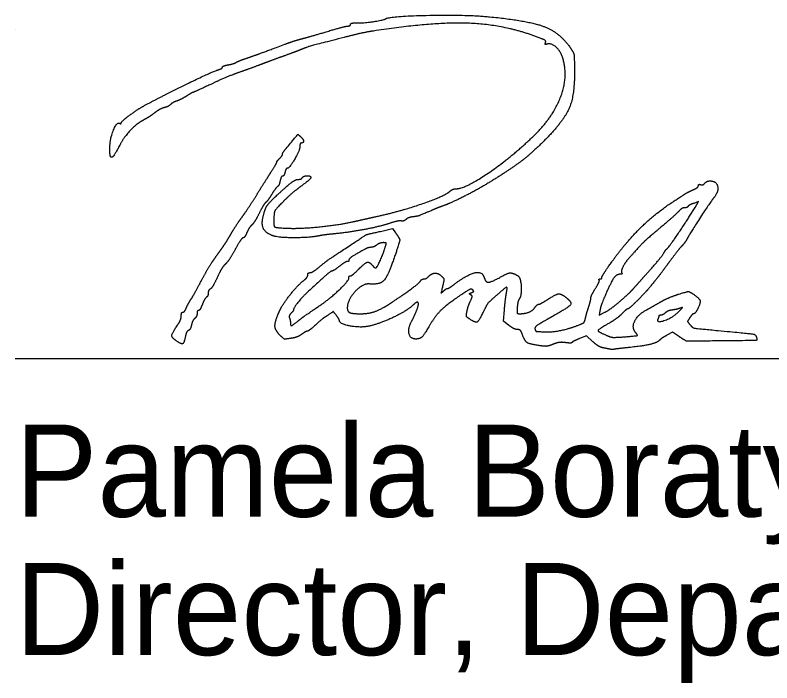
# Model space of a CAD drawing. Extents: x 0 to 48.6, y 0 to 22.
# Drawn here: x 24.528 to 25.676, y 7.305 to 8.318 of the extents above; entities that cross this region are included whole.
import ezdxf

# ---------------------------------------------------------------- set-up
doc = ezdxf.new("R2010")
doc.units = 0
for name, color, linetype in [('Default', 7, 'Continuous'), ('SH_Data', 7, 'Continuous'), ('SH_Text', 7, 'Continuous')]:
    doc.layers.add(name, color=color, linetype=linetype)

msp = doc.modelspace()

# ---------------------------------------------------------------- linework, layer by layer
at = {"layer": 'Default'}
for points in [[(25.5597, 8.0263), (25.5651, 8.0352), (25.5577, 8.0326)], [(25.0824, 7.9901), (25.1004, 7.9942), (25.1051, 7.988)], [(25.2773, 7.8473), (25.269, 7.8536), (25.2704, 7.8707)], [(25.4153, 7.8693), (25.4143, 7.8628), (25.4229, 7.8673)], [(25.5361, 7.83), (25.5255, 7.8368), (25.5171, 7.8323)], [(25.4043, 7.823), (25.3951, 7.8313), (25.3845, 7.8272)]]:
    msp.add_lwpolyline(points, dxfattribs=at)
for points in [[(25.0898, 8.3127), (25.0966, 8.3169), (25.2136, 8.3192), (25.248, 8.3158)], [(25.248, 8.3158), (25.3072, 8.31), (25.3548, 8.2917), (25.3706, 8.2686)], [(25.033, 8.3018), (25.0351, 8.3018), (25.0368, 8.3029), (25.0368, 8.3043)], [(25.0368, 8.3043), (25.0368, 8.3056), (25.0408, 8.3066), (25.0458, 8.3065)], [(25.0458, 8.3065), (25.0554, 8.3062), (25.0864, 8.3106), (25.0898, 8.3127)], [(25.3205, 8.285), (25.2699, 8.304), (25.1619, 8.308), (25.0716, 8.2942)], [(24.9612, 8.282), (24.9665, 8.2833), (24.9839, 8.2883), (25, 8.2931)], [(25, 8.2931), (25.0161, 8.2979), (25.031, 8.3018), (25.033, 8.3018)], [(25.0716, 8.2942), (25.0623, 8.2928), (25.0424, 8.2885), (25.0272, 8.2845)], [(24.9372, 8.2741), (24.9451, 8.2771), (24.9559, 8.2806), (24.9612, 8.282)], [(25.0272, 8.2845), (24.9762, 8.2714), (24.9719, 8.2701), (24.9612, 8.2658)], [(25.3328, 8.2764), (25.3338, 8.2789), (25.3303, 8.2813), (25.3205, 8.285)], [(24.8808, 8.2535), (24.8955, 8.2586), (24.9019, 8.261), (24.9372, 8.2741)], [(25.3352, 8.2743), (25.3326, 8.2733), (25.3319, 8.274), (25.3328, 8.2764)], [(25.3586, 8.2544), (25.3553, 8.2642), (25.3409, 8.2765), (25.3352, 8.2743)], [(24.9612, 8.2658), (24.9585, 8.2647), (24.9483, 8.2609), (24.9384, 8.2573)], [(25.3706, 8.2686), (25.3755, 8.2614), (25.3764, 8.257), (25.3768, 8.2392)], [(24.8514, 8.2429), (24.8563, 8.2438), (24.8615, 8.2454), (24.8628, 8.2464)], [(24.8628, 8.2464), (24.8641, 8.2473), (24.8722, 8.2506), (24.8808, 8.2535)], [(24.9384, 8.2573), (24.9285, 8.2537), (24.9134, 8.2481), (24.9048, 8.2449)], [(25.3131, 8.1332), (25.344, 8.1627), (25.3679, 8.2262), (25.3586, 8.2544)], [(24.7248, 8.1814), (24.755, 8.1976), (24.8286, 8.2333), (24.837, 8.2357)], [(24.837, 8.2357), (24.84, 8.2366), (24.8424, 8.2382), (24.8424, 8.2393)], [(24.8424, 8.2393), (24.8424, 8.2403), (24.8464, 8.242), (24.8514, 8.2429)], [(24.9048, 8.2449), (24.8962, 8.2416), (24.88, 8.2357), (24.8688, 8.2317)], [(25.3768, 8.2392), (25.3775, 8.1984), (25.3614, 8.1587), (25.332, 8.1288)], [(24.8688, 8.2317), (24.8576, 8.2278), (24.8372, 8.2192), (24.8236, 8.2127)], [(24.8236, 8.2127), (24.8099, 8.2063), (24.7983, 8.201), (24.7977, 8.201)], [(24.7977, 8.201), (24.7971, 8.201), (24.7927, 8.1984), (24.7877, 8.1953)], [(24.7877, 8.1953), (24.7828, 8.1922), (24.7761, 8.1888), (24.7729, 8.1878)], [(24.6888, 8.1547), (24.6888, 8.1569), (24.7142, 8.1757), (24.7248, 8.1814)], [(24.754, 8.1778), (24.7505, 8.1769), (24.7438, 8.1733), (24.7392, 8.1697)], [(24.7637, 8.1826), (24.7619, 8.1808), (24.7576, 8.1787), (24.754, 8.1778)], [(24.7729, 8.1878), (24.7697, 8.1868), (24.7655, 8.1844), (24.7637, 8.1826)], [(24.7392, 8.1697), (24.7346, 8.1661), (24.7274, 8.1615), (24.7233, 8.1594)], [(24.6716, 8.1169), (24.6717, 8.1301), (24.6823, 8.1567), (24.6865, 8.1541)], [(24.6865, 8.1541), (24.6877, 8.1533), (24.6888, 8.1536), (24.6888, 8.1547)], [(24.7233, 8.1594), (24.7129, 8.1541), (24.693, 8.1332), (24.6868, 8.1211)], [(24.939, 8.1158), (24.9575, 8.1379), (24.9568, 8.1374), (24.9609, 8.134)], [(24.9609, 8.134), (24.9652, 8.1304), (24.9661, 8.1242), (24.9624, 8.1242)], [(25.1964, 8.0546), (25.2105, 8.0546), (25.2786, 8.1005), (25.3131, 8.1332)], [(24.6868, 8.1211), (24.6801, 8.1082), (24.6748, 8.1013), (24.673, 8.1032)], [(24.9624, 8.1242), (24.9611, 8.1242), (24.96, 8.1219), (24.96, 8.1191)], [(25.332, 8.1288), (25.3134, 8.1099), (25.281, 8.085), (25.2505, 8.0662)], [(24.673, 8.1032), (24.6722, 8.104), (24.6716, 8.1101), (24.6716, 8.1169)], [(24.9336, 8.1072), (24.9336, 8.1084), (24.936, 8.1123), (24.939, 8.1158)], [(24.96, 8.1191), (24.96, 8.1135), (24.9441, 8.0858), (24.9409, 8.0858)], [(24.925, 8.0954), (24.9245, 8.0954), (24.9261, 8.0975), (24.9288, 8.1002)], [(24.9288, 8.1002), (24.9314, 8.1028), (24.9336, 8.1059), (24.9336, 8.1072)], [(24.916, 8.0797), (24.9216, 8.0883), (24.9256, 8.0954), (24.925, 8.0954)], [(24.9409, 8.0858), (24.9398, 8.0858), (24.9382, 8.0831), (24.9374, 8.0798)], [(24.894, 8.0447), (24.9006, 8.0553), (24.9105, 8.0711), (24.916, 8.0797)], [(24.9337, 8.0738), (24.9325, 8.0738), (24.9309, 8.0705), (24.93, 8.0666)], [(24.9374, 8.0798), (24.9366, 8.0765), (24.9349, 8.0738), (24.9337, 8.0738)], [(24.9636, 8.0714), (24.9654, 8.0743), (24.9768, 8.0746), (24.9768, 8.0717)], [(24.9252, 8.0448), (24.9409, 8.0594), (24.9536, 8.069), (24.9576, 8.069)], [(24.93, 8.0666), (24.9291, 8.0626), (24.9274, 8.0588), (24.9261, 8.058)], [(24.9576, 8.069), (24.9601, 8.069), (24.9628, 8.07), (24.9636, 8.0714)], [(24.9768, 8.0717), (24.9768, 8.0706), (24.97, 8.0647), (24.9618, 8.0586)], [(25.2505, 8.0662), (25.2313, 8.0543), (25.1901, 8.0333), (25.176, 8.0282)], [(25.5682, 8.061), (25.5701, 8.0602), (25.5729, 8.0612), (25.5745, 8.0631)], [(25.5745, 8.0631), (25.5761, 8.065), (25.5798, 8.0666), (25.5827, 8.0666)], [(25.5827, 8.0666), (25.5921, 8.0666), (25.5959, 8.0505), (25.5885, 8.0415)], [(24.9261, 8.058), (24.9248, 8.0572), (24.921, 8.0521), (24.9176, 8.0466)], [(24.9618, 8.0586), (24.9535, 8.0525), (24.941, 8.0416), (24.934, 8.0345)], [(25.0764, 8.0126), (25.1133, 8.0208), (25.1796, 8.0437), (25.1882, 8.0512)], [(25.1882, 8.0512), (25.1903, 8.0531), (25.1939, 8.0546), (25.1964, 8.0546)], [(25.528, 8.0362), (25.5469, 8.0484), (25.5488, 8.0495), (25.557, 8.0532)], [(25.557, 8.0532), (25.5613, 8.0551), (25.5648, 8.058), (25.5648, 8.0595)], [(25.5648, 8.0595), (25.5648, 8.061), (25.5663, 8.0617), (25.5682, 8.061)], [(24.8722, 8.0117), (24.8776, 8.0192), (24.8874, 8.034), (24.894, 8.0447)], [(24.9038, 8.0102), (24.9066, 8.0232), (24.9127, 8.0332), (24.9252, 8.0448)], [(24.9176, 8.0466), (24.9142, 8.0411), (24.9101, 8.0355), (24.9084, 8.0341)], [(25.5885, 8.0415), (25.5843, 8.0365), (25.5515, 7.9861), (25.5483, 7.9799)], [(24.9084, 8.0341), (24.9068, 8.0328), (24.9021, 8.0252), (24.8981, 8.0172)], [(24.934, 8.0345), (24.9233, 8.0235), (24.9211, 8.0199), (24.9206, 8.0116)], [(25.176, 8.0282), (25.1714, 8.0266), (25.1643, 8.0238), (25.1603, 8.022)], [(25.4334, 7.9437), (25.4556, 7.9745), (25.5007, 8.0185), (25.528, 8.0362)], [(25.549, 8.0279), (25.5483, 8.0267), (25.5459, 8.0258), (25.5437, 8.0258)], [(25.5577, 8.0326), (25.5537, 8.0312), (25.5498, 8.0291), (25.549, 8.0279)], [(24.8981, 8.0172), (24.8941, 8.0092), (24.889, 8.0012), (24.8868, 7.9994)], [(25.1603, 8.022), (25.1433, 8.0146), (25.1384, 8.0129), (25.1318, 8.0121)], [(25.5349, 8.0204), (25.5322, 8.0174), (25.5197, 8.0063), (25.5072, 7.9958)], [(25.5169, 7.9634), (25.5197, 7.9653), (25.5479, 8.0068), (25.5597, 8.0263)], [(25.5437, 8.0258), (25.5415, 8.0258), (25.5375, 8.0233), (25.5349, 8.0204)], [(24.8555, 7.9862), (24.8593, 7.9928), (24.8669, 8.0043), (24.8722, 8.0117)], [(24.9192, 7.9833), (24.9087, 7.9872), (24.9016, 7.9997), (24.9038, 8.0102)], [(24.9206, 8.0116), (24.9197, 7.9982), (24.9238, 7.9953), (24.9444, 7.9947)], [(24.9444, 7.9947), (24.9636, 7.9942), (25.0215, 8.0003), (25.0428, 8.0051)], [(25.0428, 8.0051), (25.0507, 8.0069), (25.0658, 8.0103), (25.0764, 8.0126)], [(25.1142, 8.0059), (25.1125, 8.0065), (25.1044, 8.0048), (25.0962, 8.0022)], [(25.121, 8.0081), (25.1189, 8.0063), (25.1158, 8.0053), (25.1142, 8.0059)], [(25.1318, 8.0121), (25.1279, 8.0117), (25.123, 8.0099), (25.121, 8.0081)], [(24.8868, 7.9994), (24.8847, 7.9976), (24.8814, 7.9925), (24.8796, 7.9881)], [(25.0962, 8.0022), (25.0797, 7.9969), (25.0346, 7.9884), (25.0108, 7.9861)], [(25.5072, 7.9958), (25.4876, 7.9793), (25.4759, 7.9679), (25.4592, 7.949)], [(24.8425, 7.9655), (24.8458, 7.9703), (24.8517, 7.9796), (24.8555, 7.9862)], [(24.8796, 7.9881), (24.8777, 7.9838), (24.8752, 7.9802), (24.8739, 7.9802)], [(24.9904, 7.9835), (24.9767, 7.9804), (24.9272, 7.9803), (24.9192, 7.9833)], [(25.0108, 7.9861), (25.0025, 7.9853), (24.9933, 7.9841), (24.9904, 7.9835)], [(25.0284, 7.9637), (25.06, 7.9847), (25.0614, 7.9854), (25.0824, 7.9901)], [(25.1051, 7.988), (25.1117, 7.9792), (25.1115, 7.9744), (25.1038, 7.9518)], [(24.8739, 7.9802), (24.8726, 7.9802), (24.8672, 7.9723), (24.8618, 7.9626)], [(25.0864, 7.9729), (25.0835, 7.9728), (25.0791, 7.9712), (25.0765, 7.9693)], [(25.0897, 7.9664), (25.0914, 7.9721), (25.091, 7.9729), (25.0864, 7.9729)], [(25.5483, 7.9799), (25.5466, 7.9764), (25.5427, 7.971), (25.5397, 7.9678)], [(24.8289, 7.9463), (24.833, 7.9521), (24.8391, 7.9608), (24.8425, 7.9655)], [(24.8618, 7.9626), (24.8565, 7.9529), (24.8498, 7.9429), (24.847, 7.9404)], [(24.9892, 7.9358), (25.0029, 7.9468), (25.0009, 7.9455), (25.0284, 7.9637)], [(25.0581, 7.9626), (25.0436, 7.9547), (25.0344, 7.9483), (25.0344, 7.9463)], [(25.0678, 7.9658), (25.0656, 7.9658), (25.0612, 7.9643), (25.0581, 7.9626)], [(25.0765, 7.9693), (25.074, 7.9673), (25.07, 7.9658), (25.0678, 7.9658)], [(25.075, 7.9346), (25.0768, 7.9346), (25.0866, 7.9557), (25.0897, 7.9664)], [(25.513, 7.9582), (25.5142, 7.9604), (25.5159, 7.9627), (25.5169, 7.9634)], [(25.5397, 7.9678), (25.5367, 7.9645), (25.5278, 7.9532), (25.5199, 7.9425)], [(25.1038, 7.9518), (25.0935, 7.9219), (25.0815, 7.9088), (25.0656, 7.9102)], [(25.4592, 7.949), (25.4533, 7.9424), (25.4471, 7.9295), (25.4485, 7.9271)], [(25.4817, 7.9204), (25.497, 7.9375), (25.5106, 7.9539), (25.513, 7.9582)], [(24.81, 7.9142), (24.8163, 7.926), (24.8248, 7.9405), (24.8289, 7.9463)], [(24.847, 7.9404), (24.8441, 7.9378), (24.8386, 7.9287), (24.8347, 7.9202)], [(25.02, 7.937), (25.015, 7.933), (25.01, 7.9298), (25.0088, 7.9297)], [(25.0317, 7.9442), (25.0303, 7.9442), (25.025, 7.9409), (25.02, 7.937)], [(25.0344, 7.9463), (25.0344, 7.9451), (25.0332, 7.9442), (25.0317, 7.9442)], [(25.0488, 7.9322), (25.0589, 7.9423), (25.0654, 7.9441), (25.0704, 7.9382)], [(25.0704, 7.9382), (25.072, 7.9362), (25.0741, 7.9346), (25.075, 7.9346)], [(25.4184, 7.9203), (25.4184, 7.9217), (25.4251, 7.9322), (25.4334, 7.9437)], [(25.5199, 7.9425), (25.512, 7.9319), (25.5043, 7.9217), (25.5029, 7.9199)], [(24.972, 7.9239), (24.972, 7.9258), (24.9735, 7.9274), (24.9754, 7.9274)], [(25.0088, 7.9297), (25.0069, 7.9297), (24.9985, 7.9225), (24.9732, 7.8992)], [(24.9754, 7.9274), (24.9772, 7.9274), (24.9834, 7.9311), (24.9892, 7.9358)], [(25.0368, 7.9226), (25.0381, 7.9226), (25.0435, 7.9269), (25.0488, 7.9322)], [(25.1555, 7.9217), (25.1605, 7.9266), (25.1705, 7.9267), (25.1754, 7.9217)], [(25.1935, 7.9091), (25.2138, 7.9243), (25.2365, 7.9299), (25.2395, 7.9204)], [(25.2633, 7.9201), (25.2752, 7.9267), (25.2825, 7.9274), (25.2907, 7.9228)], [(25.4462, 7.925), (25.4399, 7.925), (25.4304, 7.9098), (25.4183, 7.8806)], [(25.4485, 7.9271), (25.4493, 7.9259), (25.4482, 7.925), (25.4462, 7.925)], [(24.7946, 7.8866), (24.7968, 7.8899), (24.8037, 7.9023), (24.81, 7.9142)], [(24.8347, 7.9202), (24.8307, 7.9116), (24.826, 7.9037), (24.8242, 7.9026)], [(24.9285, 7.8679), (24.933, 7.8783), (24.9562, 7.9078), (24.9666, 7.9161)], [(24.9666, 7.9161), (24.9695, 7.9185), (24.972, 7.922), (24.972, 7.9239)], [(24.9883, 7.876), (25.0039, 7.8864), (25.0344, 7.9151), (25.0344, 7.9194)], [(25.0344, 7.9194), (25.0344, 7.9212), (25.0355, 7.9226), (25.0368, 7.9226)], [(25.1004, 7.8829), (25.119, 7.8953), (25.1414, 7.9119), (25.1431, 7.9147)], [(25.1431, 7.9147), (25.1442, 7.9164), (25.1465, 7.9178), (25.1483, 7.9178)], [(25.1483, 7.9178), (25.1501, 7.9178), (25.1534, 7.9195), (25.1555, 7.9217)], [(25.1754, 7.9217), (25.1786, 7.9186), (25.1788, 7.9161), (25.1767, 7.907)], [(25.2395, 7.9204), (25.2419, 7.9128), (25.25, 7.9127), (25.2633, 7.9201)], [(25.2907, 7.9228), (25.2951, 7.9203), (25.2967, 7.8923), (25.2928, 7.8872)], [(25.4086, 7.9035), (25.4125, 7.9097), (25.415, 7.9155), (25.4142, 7.9163)], [(25.4142, 7.9163), (25.4134, 7.9171), (25.414, 7.9178), (25.4156, 7.9178)], [(25.4156, 7.9178), (25.4171, 7.9178), (25.4184, 7.9189), (25.4184, 7.9203)], [(25.4661, 7.9029), (25.4692, 7.9065), (25.4762, 7.9143), (25.4817, 7.9204)], [(25.5029, 7.9199), (25.4896, 7.9034), (25.485, 7.8983), (25.4732, 7.8861)], [(24.8242, 7.9026), (24.8223, 7.9016), (24.8208, 7.8987), (24.8208, 7.8962)], [(25.0656, 7.9102), (25.0552, 7.9111), (25.032, 7.8857), (25.032, 7.8735)], [(25.1767, 7.907), (25.1744, 7.8967), (25.1745, 7.8962), (25.1783, 7.8997)], [(25.1783, 7.8997), (25.1805, 7.9017), (25.1832, 7.9034), (25.1841, 7.9034)], [(25.1841, 7.9034), (25.1851, 7.9034), (25.1893, 7.9059), (25.1935, 7.9091)], [(25.2222, 7.9013), (25.2204, 7.9031), (25.2145, 7.9003), (25.202, 7.8918)], [(25.2734, 7.8956), (25.2752, 7.905), (25.2726, 7.9054), (25.2633, 7.8972)], [(25.4016, 7.8887), (25.4016, 7.8905), (25.4047, 7.8972), (25.4086, 7.9035)], [(25.446, 7.8841), (25.4539, 7.8909), (25.4629, 7.8994), (25.4661, 7.9029)], [(24.8183, 7.8901), (24.8169, 7.8892), (24.8141, 7.8843), (24.812, 7.8792)], [(24.8208, 7.8962), (24.8208, 7.8937), (24.8197, 7.8909), (24.8183, 7.8901)], [(24.9732, 7.8992), (24.9641, 7.8909), (24.9504, 7.8738), (24.9504, 7.8708)], [(25.202, 7.8918), (25.1823, 7.8784), (25.1651, 7.8613), (25.1568, 7.847)], [(25.2194, 7.8936), (25.2172, 7.895), (25.2175, 7.8959), (25.2206, 7.8971)], [(25.2187, 7.8838), (25.2215, 7.8901), (25.2217, 7.8922), (25.2194, 7.8936)], [(25.2206, 7.8971), (25.2236, 7.8982), (25.224, 7.8995), (25.2222, 7.9013)], [(25.2633, 7.8972), (25.2474, 7.8832), (25.2437, 7.8788), (25.2382, 7.8674)], [(25.2704, 7.8707), (25.2712, 7.8801), (25.2726, 7.8913), (25.2734, 7.8956)], [(25.336, 7.8866), (25.3489, 7.8948), (25.3565, 7.8956), (25.3642, 7.8895)], [(25.506, 7.8821), (25.5139, 7.8866), (25.5271, 7.8923), (25.5353, 7.8948)], [(25.5353, 7.8948), (25.5493, 7.899), (25.5505, 7.899), (25.5564, 7.8952)], [(25.5564, 7.8952), (25.566, 7.8889), (25.5684, 7.8815), (25.5638, 7.8725)], [(24.7877, 7.874), (24.7893, 7.8776), (24.7924, 7.8833), (24.7946, 7.8866)], [(24.812, 7.8792), (24.81, 7.874), (24.8073, 7.8698), (24.8061, 7.8698)], [(25.0519, 7.865), (25.065, 7.865), (25.0841, 7.872), (25.1004, 7.8829)], [(25.1324, 7.8787), (25.1228, 7.8696), (25.084, 7.8508), (25.0656, 7.8463)], [(25.1294, 7.853), (25.1335, 7.8606), (25.14, 7.8769), (25.14, 7.8797)], [(25.14, 7.8797), (25.14, 7.8827), (25.136, 7.8822), (25.1324, 7.8787)], [(25.2136, 7.8682), (25.2144, 7.8723), (25.2166, 7.8794), (25.2187, 7.8838)], [(25.2928, 7.8872), (25.2916, 7.8855), (25.2903, 7.8798), (25.2899, 7.8746)], [(25.3168, 7.8745), (25.3187, 7.8772), (25.3212, 7.8794), (25.3224, 7.8794)], [(25.3224, 7.8794), (25.3236, 7.8794), (25.3297, 7.8826), (25.336, 7.8866)], [(25.3642, 7.8895), (25.3739, 7.8819), (25.367, 7.874), (25.3354, 7.8563)], [(25.3981, 7.8746), (25.4, 7.8805), (25.4016, 7.8869), (25.4016, 7.8887)], [(25.4183, 7.8806), (25.4172, 7.8779), (25.4159, 7.8728), (25.4153, 7.8693)], [(25.4229, 7.8673), (25.4277, 7.8697), (25.4381, 7.8773), (25.446, 7.8841)], [(25.4732, 7.8861), (25.4657, 7.8784), (25.4586, 7.8722), (25.4576, 7.8722)], [(25.4864, 7.8711), (25.4893, 7.8726), (25.4981, 7.8776), (25.506, 7.8821)], [(24.78, 7.8617), (24.78, 7.8648), (24.7811, 7.8674), (24.7824, 7.8674)], [(24.7824, 7.8674), (24.7838, 7.8674), (24.7862, 7.8703), (24.7877, 7.874)], [(24.8061, 7.8698), (24.8049, 7.8698), (24.804, 7.8677), (24.804, 7.8653)], [(24.9302, 7.8322), (24.9225, 7.8398), (24.9219, 7.8526), (24.9285, 7.8679)], [(24.9504, 7.8708), (24.9504, 7.87), (24.9487, 7.8677), (24.9466, 7.8657)], [(24.9568, 7.8536), (24.9643, 7.8597), (24.9696, 7.8635), (24.9883, 7.876)], [(25.0154, 7.8624), (25.0109, 7.8682), (25.0108, 7.8682), (25.0041, 7.8638)], [(25.032, 7.8735), (25.032, 7.8683), (25.0398, 7.865), (25.0519, 7.865)], [(25.2182, 7.8566), (25.2132, 7.8599), (25.2124, 7.8619), (25.2136, 7.8682)], [(25.2382, 7.8674), (25.2315, 7.8537), (25.2267, 7.8511), (25.2182, 7.8566)], [(25.2899, 7.8746), (25.2894, 7.867), (25.2901, 7.865), (25.2932, 7.865)], [(25.2932, 7.865), (25.3016, 7.865), (25.3136, 7.8698), (25.3168, 7.8745)], [(25.3933, 7.8575), (25.394, 7.8609), (25.3961, 7.8686), (25.3981, 7.8746)], [(25.4576, 7.8722), (25.4565, 7.8722), (25.4526, 7.869), (25.449, 7.8652)], [(25.4694, 7.8367), (25.4633, 7.8441), (25.4731, 7.8639), (25.4864, 7.8711)], [(25.5033, 7.8568), (25.5008, 7.8503), (25.5263, 7.8593), (25.5348, 7.8679)], [(25.5254, 7.8707), (25.5215, 7.8702), (25.5166, 7.8681), (25.5144, 7.8662)], [(25.5372, 7.8734), (25.5345, 7.8724), (25.5292, 7.8712), (25.5254, 7.8707)], [(25.5348, 7.8679), (25.5403, 7.8735), (25.5408, 7.8748), (25.5372, 7.8734)], [(25.5638, 7.8725), (25.5616, 7.8683), (25.5589, 7.865), (25.5578, 7.865)], [(24.7742, 7.8475), (24.7774, 7.8522), (24.78, 7.8586), (24.78, 7.8617)], [(24.8005, 7.8579), (24.7986, 7.8563), (24.7964, 7.8518), (24.7955, 7.8478)], [(24.804, 7.8653), (24.804, 7.8628), (24.8024, 7.8595), (24.8005, 7.8579)], [(24.9466, 7.8657), (24.9446, 7.8636), (24.9435, 7.8604), (24.9442, 7.8585)], [(24.9442, 7.8585), (24.945, 7.8565), (24.9456, 7.8534), (24.9456, 7.8516)], [(25.0041, 7.8638), (24.9959, 7.8584), (24.9933, 7.8564), (24.9821, 7.8464)], [(25.0199, 7.855), (25.0199, 7.8559), (25.0179, 7.8592), (25.0154, 7.8624)], [(25.3354, 7.8563), (25.3222, 7.8488), (25.316, 7.844), (25.3168, 7.8418)], [(25.3806, 7.8469), (25.3894, 7.8502), (25.3923, 7.8527), (25.3933, 7.8575)], [(25.449, 7.8652), (25.4454, 7.8614), (25.4373, 7.8553), (25.431, 7.8516)], [(25.5048, 7.8616), (25.5048, 7.861), (25.5041, 7.8589), (25.5033, 7.8568)], [(25.5076, 7.8626), (25.506, 7.8626), (25.5048, 7.8621), (25.5048, 7.8616)], [(25.5144, 7.8662), (25.5122, 7.8642), (25.5091, 7.8626), (25.5076, 7.8626)], [(25.5519, 7.8591), (25.5484, 7.8538), (25.5484, 7.8529), (25.5523, 7.8482)], [(25.5578, 7.865), (25.5567, 7.865), (25.554, 7.8623), (25.5519, 7.8591)], [(24.7725, 7.8238), (24.7655, 7.8286), (24.7659, 7.8354), (24.7742, 7.8475)], [(24.7955, 7.8478), (24.7946, 7.8439), (24.7925, 7.8401), (24.7908, 7.8394)], [(24.9456, 7.8516), (24.9456, 7.8467), (24.949, 7.8473), (24.9568, 7.8536)], [(24.9821, 7.8464), (24.9773, 7.8421), (24.9725, 7.8386), (24.9714, 7.8386)], [(25.0656, 7.8463), (25.0527, 7.8433), (25.0201, 7.8494), (25.0199, 7.855)], [(25.1361, 7.8266), (25.1277, 7.8266), (25.1237, 7.8424), (25.1294, 7.853)], [(25.1568, 7.847), (25.1486, 7.8329), (25.1422, 7.8266), (25.1361, 7.8266)], [(25.2903, 7.841), (25.2877, 7.841), (25.2819, 7.8438), (25.2773, 7.8473)], [(25.3308, 7.8375), (25.3413, 7.8369), (25.3674, 7.8418), (25.3806, 7.8469)], [(25.431, 7.8516), (25.4131, 7.8412), (25.412, 7.8379), (25.425, 7.8324)], [(25.5523, 7.8482), (25.5559, 7.8437), (25.5609, 7.8427), (25.5948, 7.8395)], [(24.7908, 7.8394), (24.7891, 7.8388), (24.787, 7.8346), (24.7862, 7.8302)], [(24.9629, 7.8338), (24.9593, 7.8312), (24.9519, 7.8284), (24.9464, 7.8276)], [(24.9714, 7.8386), (24.9703, 7.8386), (24.9665, 7.8364), (24.9629, 7.8338)], [(25.2978, 7.8332), (25.296, 7.8383), (25.2934, 7.841), (25.2903, 7.841)], [(25.3232, 7.8166), (25.3082, 7.819), (25.3013, 7.8235), (25.2978, 7.8332)], [(25.3168, 7.8418), (25.3181, 7.8384), (25.3188, 7.8382), (25.3308, 7.8375)], [(25.4518, 7.8299), (25.4713, 7.8315), (25.4731, 7.8322), (25.4694, 7.8367)], [(25.5948, 7.8395), (25.6439, 7.835), (25.6521, 7.8334), (25.6531, 7.8287)], [(24.7862, 7.8302), (24.7843, 7.8205), (24.7801, 7.8185), (24.7725, 7.8238)], [(24.9464, 7.8276), (24.9377, 7.8262), (24.9355, 7.8268), (24.9302, 7.8322)], [(25.3632, 7.8211), (25.3574, 7.8219), (25.3501, 7.8209), (25.3443, 7.8186)], [(25.3733, 7.8215), (25.3729, 7.8206), (25.3683, 7.8204), (25.3632, 7.8211)], [(25.3845, 7.8272), (25.3787, 7.8249), (25.3737, 7.8224), (25.3733, 7.8215)], [(25.4189, 7.8135), (25.4159, 7.8142), (25.4093, 7.8184), (25.4043, 7.823)], [(25.425, 7.8324), (25.4318, 7.8294), (25.4383, 7.8289), (25.4518, 7.8299)], [(25.5054, 7.8244), (25.5017, 7.8207), (25.4802, 7.8158), (25.4568, 7.8134)], [(25.5171, 7.8323), (25.5125, 7.8298), (25.5072, 7.8263), (25.5054, 7.8244)], [(25.5828, 7.8236), (25.5471, 7.8232), (25.5467, 7.8232), (25.5361, 7.83)], [(25.6531, 7.8287), (25.6539, 7.8244), (25.6519, 7.8243), (25.5828, 7.8236)], [(25.3443, 7.8186), (25.3373, 7.8158), (25.3318, 7.8153), (25.3232, 7.8166)], [(25.4292, 7.8114), (25.4265, 7.8119), (25.4219, 7.8129), (25.4189, 7.8135)], [(25.4376, 7.8111), (25.4356, 7.8107), (25.4318, 7.8108), (25.4292, 7.8114)], [(25.4568, 7.8134), (25.4482, 7.8125), (25.4396, 7.8115), (25.4376, 7.8111)]]:
    msp.add_open_spline(points, degree=2, dxfattribs=at)
at = {"layer": 'SH_Data'}
for p, q in [((24.5279, 8.2968), (24.5279, 8.2968)), ((24.5279, 7.7968), (28.0279, 7.7968))]:
    msp.add_line(p, q, dxfattribs=at)

# ---------------------------------------------------------------- texts
at = {"layer": 'SH_Text'}
for s, p in [('Pamela Boratyn', (24.5279, 7.5568)), ('Director, Department of Transportation', (24.5279, 7.3468))]:
    msp.add_text(s, height=0.14, dxfattribs=at).set_placement(p)

doc.saveas('drawing.dxf')
